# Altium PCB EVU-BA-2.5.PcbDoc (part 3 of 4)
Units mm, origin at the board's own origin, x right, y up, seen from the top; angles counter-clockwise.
Board outline 80 x 82.5 mm, 4 copper layers (Top Layer, Int1, Int2, Bottom Layer), stack 1.49 mm thick; 257 components, 201 nets, 889 pads, 696 vias.
Unrouted connection lines stored in the file: 1.
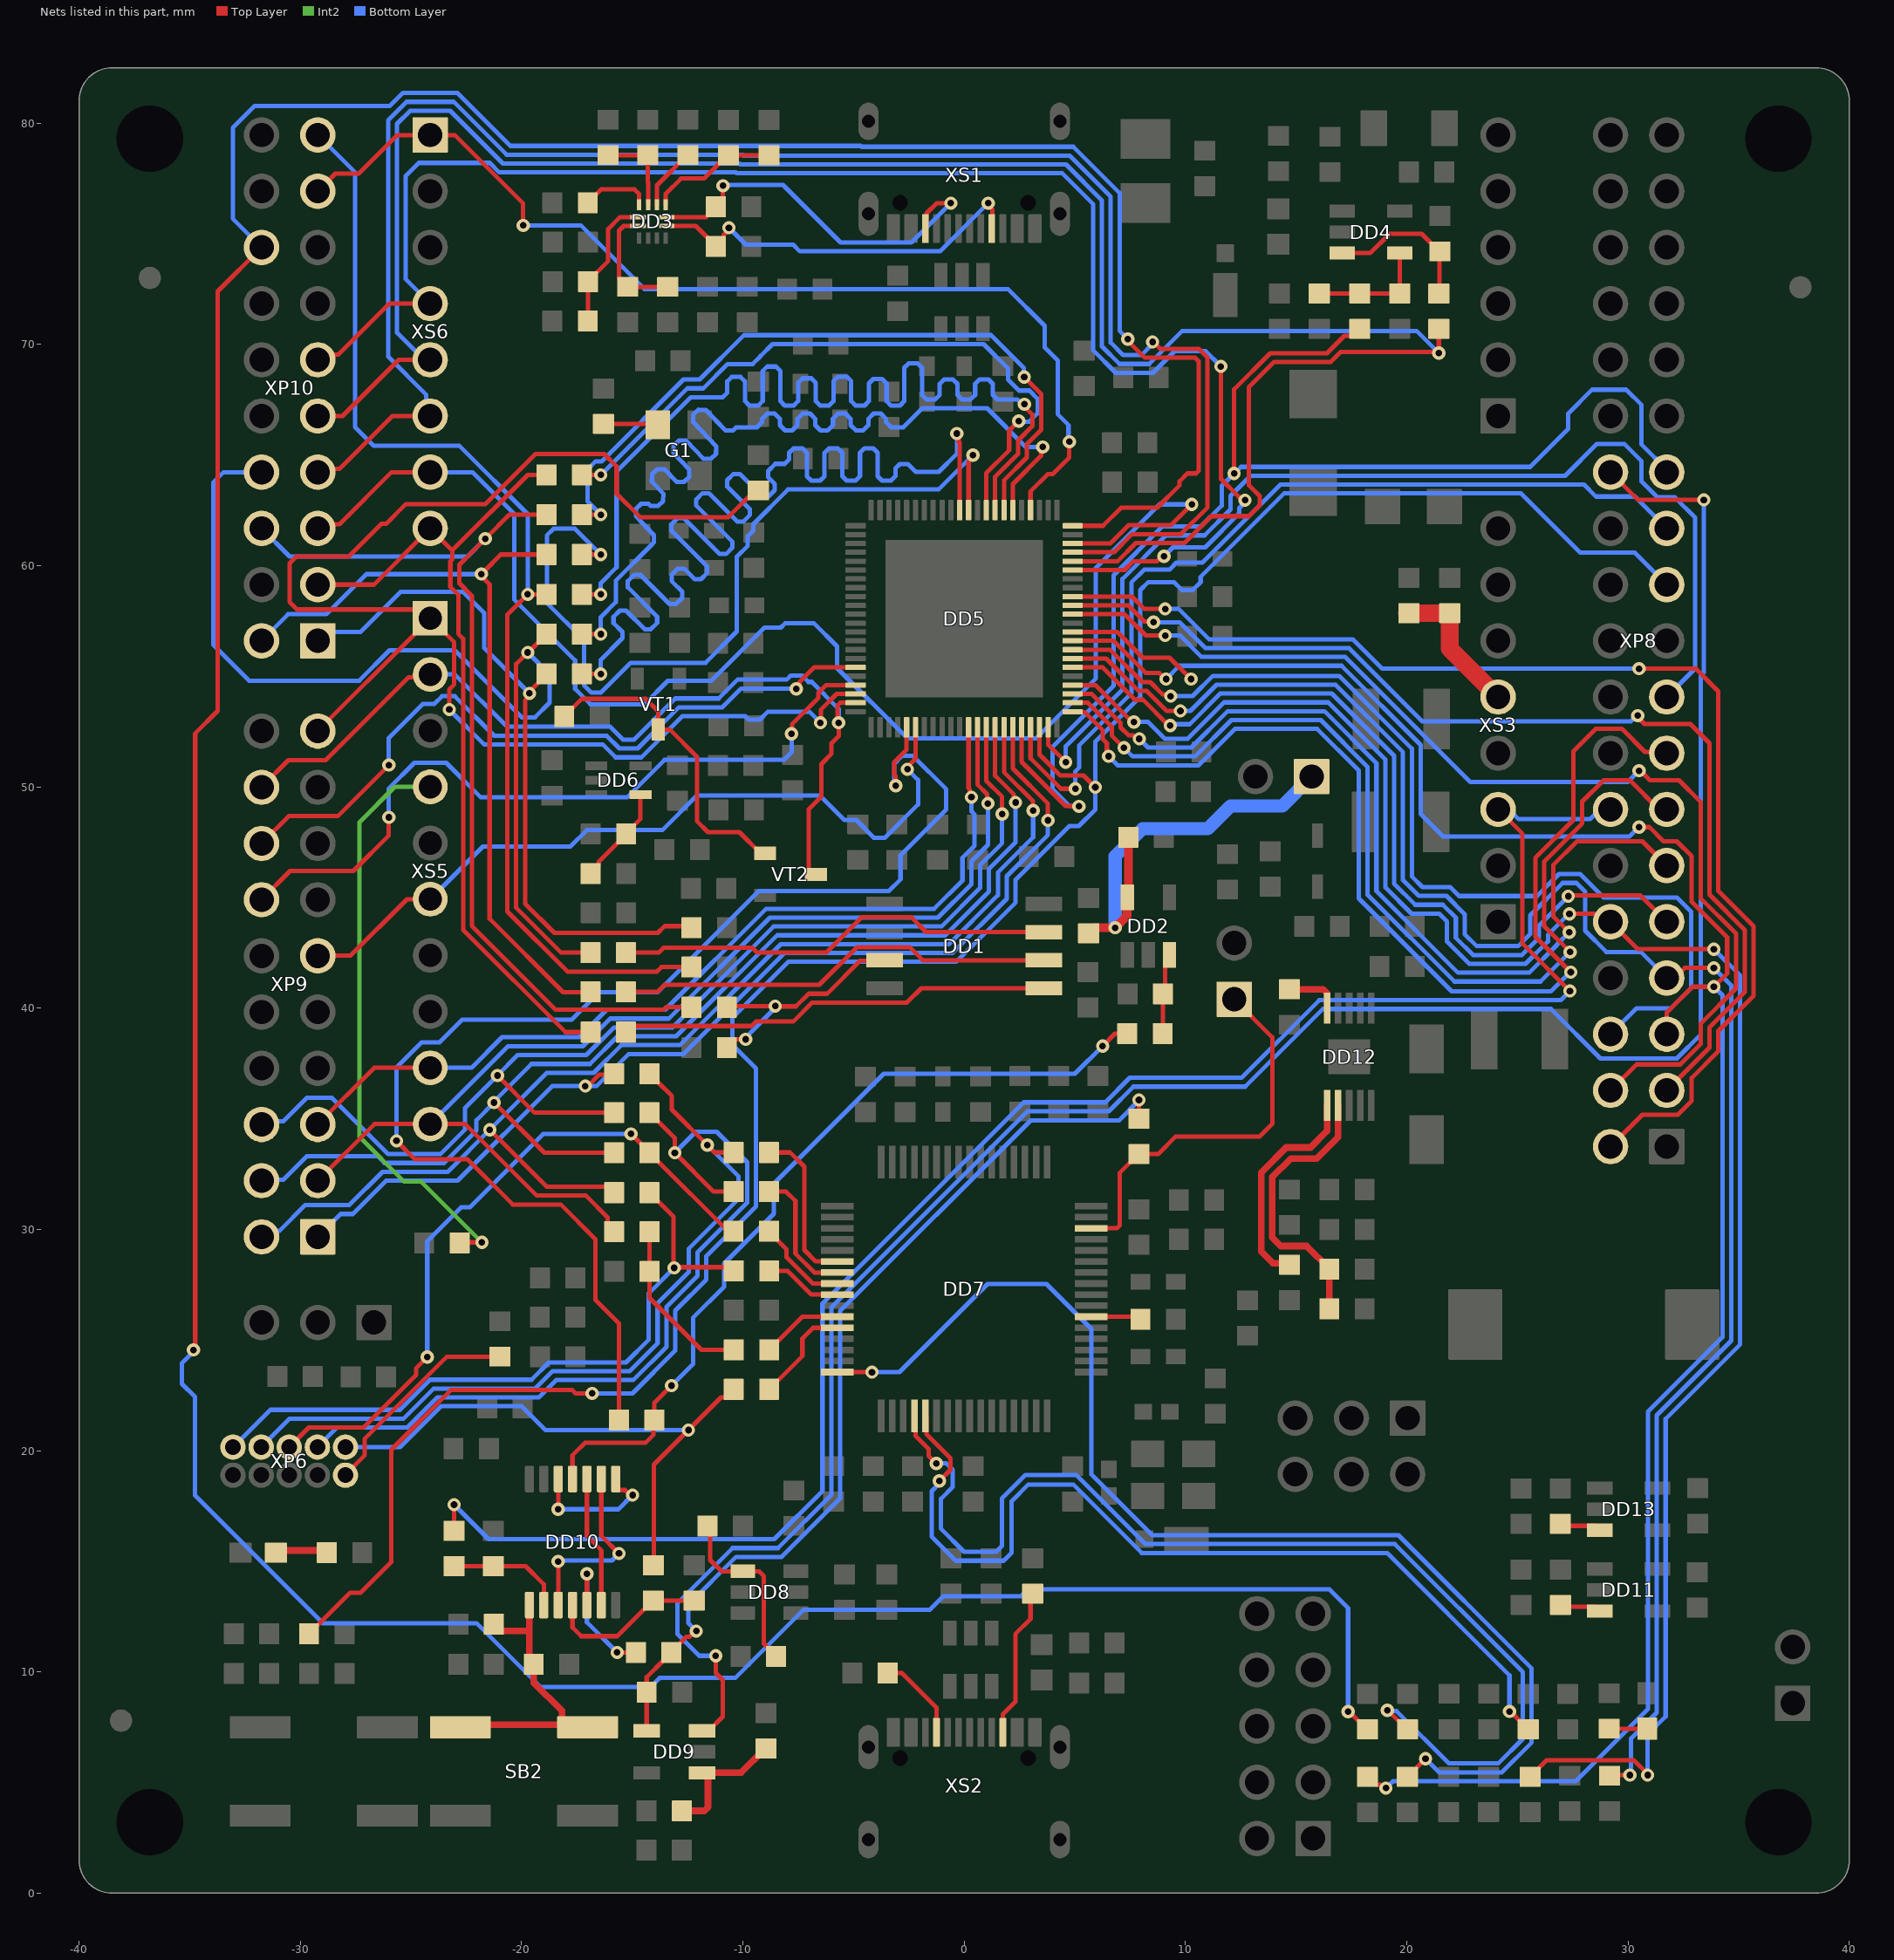
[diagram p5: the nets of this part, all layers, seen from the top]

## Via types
v1: diameter 0.6, hole 0.3, Top Layer to Bottom Layer, tented both sides, 670 vias
v2: diameter 0.6, hole 0.3, Top Layer to Bottom Layer, tented bottom, 26 vias

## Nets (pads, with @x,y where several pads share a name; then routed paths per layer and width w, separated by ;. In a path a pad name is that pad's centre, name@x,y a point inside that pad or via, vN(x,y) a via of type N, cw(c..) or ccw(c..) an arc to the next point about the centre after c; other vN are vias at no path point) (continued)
NetDD1_3: DD1.3 R2.2 R3.1 | length 11
  Top Layer w0.2: R2.2@-10.723,38.284 -10.417,38.589 v1(-9.873,38.589) ; R3.1@-10.723,40.039 -10.672,40.09 v1(-8.538,40.09) -8.524,40.076 -7.602,40.076 -7.028,40.65 -6.191,40.65 -4.708,42.133 -3.632,42.133 DD1.3@-3.6,42.165
  Bottom Layer w0.2: v1(-9.873,38.589) -9.873,38.672 -8.538,40.007 v1(-8.538,40.09)
NetDD1_5: DD1.5 R27.2 | length 19.7
  Top Layer w0.2: R27.2@-15.285,38.914 -15.01,39.189 -9.607,39.189 -9.407,39.389 -7.723,39.389 -6.862,40.25 -2.587,40.25 -1.942,40.895 DD1.5@3.6,40.895
NetDD1_6: DD1.6 R26.2 | length 20
  Top Layer w0.2: R26.2@-15.335,40.73 -13.863,40.73 -13.543,41.05 -6.546,41.05 -4.856,42.74 -2.444,42.74 -1.869,42.165 DD1.6@3.6,42.165
NetDD1_7: DD1.7 R25.2 | length 20
  Top Layer w0.2: R25.2@-15.285,42.505 -13.805,42.505 -13.58,42.73 -9.574,42.73 -9.349,42.505 -6.237,42.505 -4.643,44.1 -2.383,44.1 -1.718,43.435 DD1.7@3.6,43.435
NetDD2_3: DD2.3 R6.2 R8.2 | length 3.7
  Top Layer w0.2: R8.2@8.971,38.845 8.979,38.853 8.979,40.637 R6.2@8.987,40.645 9.075,40.733 9.075,42.205 DD2.3@9.275,42.405
NetDD2_5: DD2.5 R23.2 R24.1 XP2.1 | length 20
  Top Layer w0.4: R24.1@5.621,43.38 5.871,43.63 v1@6.867,43.63 ; v1(6.825,43.63) 7.368,44.173 DD2.5@7.368,44.864 ; 7.347,44.11 7.347,44.977 DD2.5@7.375,45.005 ; DD2.5@7.419,45.049 R23.2@7.419,47.72
  Bottom Layer w0.6: v1(6.825,43.63) 6.825,46.864 8.066,48.105 11.007,48.105 12.042,49.14 14.376,49.14 XP2.1@15.703,50.467
NetDD3_1: DD3.1 R15.2 XS1.A5 | length 18
  Top Layer w0.2: DD3.1@-13.436,75.352 -12.126,75.352 R15.2@-11.218,74.444 ; R15.2@-11.218,74.419 R15.2@-11.218,74.444 ; v1(-10.63,75.269) -10.63,75.191 -10.868,74.952 -10.868,74.794 R15.2@-11.218,74.444 ; v1(1.087,76.382) 1.087,76.274 1.27,76.091 1.27,75.25 XS1.A5@1.25,75.23
  Bottom Layer w0.2: v1(-10.63,75.269) -9.86,74.5 -7.723,74.5 -7.423,74.2 -1.095,74.2 v1(1.087,76.382)
NetDD3_2: DD3.2 R13.2 XS1.B5 | length 17.6
  Top Layer w0.2: DD3.2@-13.436,75.752 -11.661,75.752 -10.9,76.512 v1(-10.9,77.17) ; XS1.B5@-1.75,75.23 -1.7,75.28 -1.7,75.92 -1.249,76.372 -0.612,76.372 v1(-0.602,76.382)
  Bottom Layer w0.2: v1(-10.9,77.17) -10.87,77.2 -8.188,77.2 -5.588,74.6 -2.384,74.6 v1(-0.602,76.382)
NetDD3_3: DD3.3 R17.2 R112.2 | length 5.8
  Top Layer w0.2: DD3.3@-13.486,76.302 -13.486,76.8 -12.792,77.495 -11.758,77.495 -11.088,78.164 -11.088,78.189 R17.2@-10.738,78.539 ; R17.2@-10.659,78.54 R112.2@-8.823,78.54
NetDD3_4: DD3.4 R16.2 | length 2.8
  Top Layer w0.2: DD3.4@-13.886,76.302 -13.886,77.182 -12.516,78.552 R16.2@-12.491,78.552
NetDD3_5: DD3.5 R30.1 R32.1 | length 4.1
  Top Layer w0.2: R30.1@-16.098,78.552 R32.1@-14.294,78.552 -14.294,77.331 -14.286,77.323 DD3.5@-14.286,76.302
NetDD3_6: DD3.6 R34.1 | length 3.2
  Top Layer w0.2: R34.1@-17.01,76.393 -17.01,76.418 -16.66,76.768 -16.635,76.768 -16.403,77 -14.9,77 -14.686,76.786 DD3.6@-14.686,76.302
NetDD3_7: DD3.7 R28.1 R31.1 | length 6.1
  Top Layer w0.2: R28.1@-17.008,71.052 -17.002,71.058 -17.002,72.824 R31.1@-16.996,72.83 -16.996,72.855 -16.086,73.764 -16.086,75.214 -15.549,75.752 DD3.7@-14.736,75.752
NetDD3_8: DD3.8 R29.1 R33.1 | length 5.4
  Top Layer w0.2: R33.1@-15.244,72.634 -15.259,72.634 -15.575,72.95 -15.575,73.042 -15.6,73.067 -15.6,75.134 -15.383,75.352 DD3.8@-14.736,75.352 ; R33.1@-15.2,72.6 R29.1@-13.4,72.6
NetDD4_3: DD4.3 R36.1 R38.1 | length 7
  Top Layer w0.2: DD4.3@17.082,74.125 18.354,74.125 19.229,75 20.675,75 21.475,74.2 R38.1@21.5,74.2 21.475,74.175 21.475,72.325 R36.1@21.45,72.3
NetDD4_4: DD4.4 R42.1 R43.1 R44.1 | length 5.7
  Top Layer w0.2: R44.1@16.05,72.3 R43.1@17.879,72.3 R42.1@19.682,72.3 19.682,73.925 19.457,74.15 DD4.4@19.375,74.15
NetDD5_49: DD5.49 R116.2 | length 61
  Top Layer w0.2: v1(-25.65,34) -24.81,33.16 -22.436,33.16 -20.401,31.125 -18.231,31.125 -16.668,29.562 -16.668,26.819 -15.599,25.75 R116.2@-15.599,21.377 ; v1(-3.095,50.048) -3.104,50.058 -3.104,50.488 -3.164,50.547 -3.164,51.118 -2.6,51.682 DD5.49@-2.6,52.695
  Bottom Layer w0.2: v1(-25.65,34) -25.65,37.318 -24.51,38.458 -23.699,38.458 -22.674,39.483 -17.728,39.483 -16.486,40.725 -13.842,40.725 -9.277,45.29 -3.402,45.29 -2.876,45.816 -2.876,46.909 -0.809,48.976 -0.809,49.889 -2.315,51.395 -2.812,51.395 -3.164,51.044 -3.164,50.117 v1(-3.095,50.048)
NetDD5_76: DD5.76 X1.1 | length 6.2
  Top Layer w0.2: DD5.76@4.905,57 6.918,57 8.079,55.84 9.282,55.84 v2(10.25,54.872)
NetDD6_4: DD6.4 R54.2 R55.1 | length 4.5
  Top Layer w0.2: R55.1@-16.875,46.075 -16.525,46.425 -16.525,46.6 -15.275,47.85 R54.2@-15.275,47.875 -15.275,47.9 -14.625,48.55 DD6.4@-14.625,49.65
NetDD7_6: DD7.6 R61.2 | length 2.3
  Top Layer w0.2: DD7.6@5.738,26.05 7.783,26.05 R61.2@7.933,26.2
NetDD7_38: DD7.38 R69.1 | length 7.3
  Top Layer w0.2: R69.1@-8.818,33.473 -7.865,33.473 -7.225,32.833 -7.225,29.07 -6.705,28.55 DD7.38@-5.738,28.55
NetDD7_39: DD7.39 R64.1 | length 6
  Top Layer w0.2: R64.1@-8.818,31.704 -8.045,31.704 -7.625,31.285 -7.625,28.905 -6.771,28.05 DD7.39@-5.738,28.05
NetDD7_40: DD7.40 R65.1 | length 4.3
  Top Layer w0.2: R65.1@-8.822,29.893 -8.025,29.097 -8.025,28.739 -6.836,27.55 DD7.40@-5.738,27.55
NetDD7_41: DD7.41 R66.1 | length 3.5
  Top Layer w0.2: R66.1@-8.811,28.126 -7.978,28.126 -6.902,27.05 DD7.41@-5.738,27.05
NetDD7_43: DD7.43 R67.1 | length 3.7
  Top Layer w0.2: R67.1@-8.811,24.55 -8.811,24.575 -8.461,24.925 -8.436,24.925 -7.311,26.05 DD7.43@-5.738,26.05
NetDD7_44: DD7.44 R68.1 | length 4.7
  Top Layer w0.2: R68.1@-8.811,22.77 -8.811,22.795 -8.461,23.145 -8.436,23.145 -7.311,24.27 -7.311,25.067 -6.828,25.55 DD7.44@-5.738,25.55
NetDD7_48: DD7.48 R100.1 | length 54.2
  Top Layer w0.2: DD7.48@-5.738,23.55 -5.735,23.547 -4.169,23.547 v1(-4.166,23.545) ; R100.1@20.03,5.25 v1(20.85,6.07)
  Bottom Layer w0.2: v1(-4.166,23.545) -2.927,23.545 1.058,27.529 3.721,27.529 5.754,25.496 5.754,18.923 8.502,16.175 19.627,16.175 25.644,10.158 25.644,6.806 24.298,5.459 21.461,5.459 v1(20.85,6.07)
NetDD7_52: DD7.52 R101.1 | length 51.3
  Top Layer w0.2: DD7.52@-2.25,21.562 -2.2,21.512 -2.2,20.67 -1.6,20.07 -1.6,19.758 v1(-1.26,19.418) ; v1(19.127,8.263) 19.148,8.263 20.008,7.403 R101.1@20.033,7.403
  Bottom Layer w0.2: v1(-1.26,19.418) -1.257,19.421 -0.809,19.421 -0.518,19.13 -0.518,18.35 -1.045,17.823 -1.045,16.466 -0.003,15.424 1.44,15.424 1.711,15.695 1.711,17.844 2.766,18.9 5.066,18.9 8.191,15.775 19.462,15.775 25.244,9.992 25.244,6.972 24.132,5.859 21.909,5.859 19.54,8.228 19.163,8.228 v1(19.127,8.263)
NetDD7_53: DD7.53 R102.1 | length 42
  Top Layer w0.2: DD7.53@-1.75,21.562 -1.7,21.512 -1.7,20.736 -0.618,19.653 -0.618,19.131 v1(-1.118,18.631) ; v1(24.644,8.209) 24.689,8.209 25.117,7.781 25.117,7.756 25.467,7.406 R102.1@25.492,7.406
  Bottom Layer w0.2: v1(-1.118,18.631) -1.118,18.523 -1.469,18.172 -1.469,16.112 -0.381,15.024 1.789,15.024 2.15,15.385 2.15,17.718 2.901,18.469 4.931,18.469 8.025,15.375 19.113,15.375 24.644,9.843 v1(24.644,8.209)
NetDD8_1: DD8.1 R59.2 R60.2 | length 8.2
  Top Layer w0.2: R59.2@-11.6,16.596 -11.475,16.471 -11.475,15.054 -10.958,14.537 -10,14.537 -9.257,14.537 -9.05,14.33 -9.05,11.275 -8.5,10.725 R60.2@-8.5,10.7
NetDD9_1: DD9.1 R77.2 R79.1 | length 6.1
  Top Layer w0.3: R79.1@-12.755,3.717 -11.751,3.717 -11.575,3.893 DD9.1@-11.575,5.437 ; DD9.1@-11.85,5.437 DD9.1@-11.575,5.437 ; R77.2@-8.955,6.537 -8.98,6.537 -10.08,5.437 DD9.1@-11.575,5.437
NetDD10_2: DD10.2 R82.1 R83.1 | length 5.3
  Top Layer w0.2: R83.1@-23.051,14.775 R82.1@-21.275,14.775 -19.814,14.775 -18.997,13.958 DD10.2@-18.997,13.017
NetDD10_3: DD10.3 DD10.9 | length 8.6
  Top Layer w0.2: DD10.3@-18.347,13.017 v1(-18.347,14.991) ; DD10.9@-16.397,18.717 -16.397,16.152 v1(-15.597,15.352)
  Bottom Layer w0.2: v1(-18.347,14.991) -18.302,15.036 -15.914,15.036 v1@-15.598,15.352
NetDD10_4: DD10.4 R85.2 R86.1 | length 7.3
  Top Layer w0.2: DD10.4@-17.697,13.017 -17.697,12.008 -17.303,11.614 -15.673,11.614 -14.071,13.217 R85.2@-14.046,13.217 R86.1@-12.2,13.217
NetDD10_5: DD10.5 R84.1 | length 6.4
  Top Layer w0.2: DD10.5@-17.047,13.017 v1(-17.047,14.436) ; v1(-15.681,10.878) R84.1@-14.831,10.878
  Bottom Layer w0.2: v1(-17.047,14.436) -17.047,12.243 v1(-15.681,10.878)
NetDD10_6: DD10.6 DD10.10 | length 6
  Top Layer w0.2: DD10.10@-17.047,18.717 -17.047,16.142 -16.397,15.492 DD10.6@-16.397,13.017
NetDD10_8: DD10.8 DD10.12 | length 6.3
  Top Layer w0.2: v1(-18.347,17.35) DD10.12@-18.347,18.717 ; DD10.8@-15.747,18.717 -15.747,18.317 -15.647,18.217 -15.32,18.217 -15.091,17.989 v1(-14.983,17.989)
  Bottom Layer w0.2: v1(-18.347,17.35) -15.622,17.35 v1(-14.983,17.989)
NetDD11_3: DD11.3 R90.2 | length 1.9
  Top Layer w0.2: R90.2@26.95,13.025 27.025,12.95 28.525,12.95 DD11.3@28.725,12.75
NetDD12_5: DD12.5 R91.2 | length 2.4
  Top Layer w0.3: R91.2@14.7,40.852 16.224,40.852 16.4,40.676 DD12.5@16.4,40
NetDD12_6: DD12.6 R95.1 | length 10
  Top Layer w0.3: R95.1@14.7,28.4 14.628,28.472 13.951,28.472 13.425,28.998 13.425,32.568 14.557,33.7 15.65,33.7 16.4,34.45 DD12.6@16.4,35.6
NetDD12_7: DD12.7 R93.1 R94.2 | length 12.9
  Top Layer w0.3: R93.1@16.5,26.4 R94.2@16.5,28.2 16.5,28.225 15.481,29.244 14.319,29.244 13.925,29.639 13.925,32.361 14.764,33.2 15.929,33.2 16.9,34.171 DD12.7@16.9,35.6
NetDD13_3: DD13.3 R96.2 | length 1.9
  Top Layer w0.2: R96.2@26.936,16.69 27.026,16.6 28.525,16.6 DD13.3@28.725,16.4
NetG1_1: G1.1 R35.2 | length 2.5
  Top Layer w0.2: R35.2@-16.3,66.4 -13.89,66.4 G1.1@-13.85,66.36
NetLD1_2: LD1.2 R87.2 | length 1.7
  Top Layer w0.2: R87.2@29.148,7.433 LD1.2@30.872,7.433
NetLD2_2: LD2.2 R97.1 | length 2.3
  Top Layer w0.3: LD2.2@-31.201,15.487 R97.1@-28.901,15.487
NetR98_1: R98.1 XP6.9 | length 9.7
  Top Layer w0.2: XP6.9@-27.959,18.888 -27.959,18.92 -27.084,19.795 -27.084,20.538 -23.376,24.246 R98.1@-20.979,24.246
NetR103_2: R103.2 VT1.3 VT2.1 | length 14.5
  Top Layer w0.2: R103.2@-18.072,53.184 -18.072,53.209 -17.722,53.559 -17.697,53.559 -17.281,53.975 -14.381,53.975 -13.821,53.415 VT1.3@-13.821,52.59 -13.3,52.59 -12.075,51.365 -12.075,48.45 -11.578,47.953 -10.157,47.953 -9.198,46.993 VT2.1@-8.998,46.993
NetR109_1: R109.1 XS2.A5 | length 4.1
  Top Layer w0.2: R109.1@-3.456,9.944 -2.811,9.944 -1.25,8.384 XS2.A5@-1.25,7.175
NetR110_1: R110.1 XS2.B5 | length 6.8
  Top Layer w0.2: XS2.B5@1.751,7.176 1.751,8.08 2.313,8.643 2.313,11.707 3,12.394 R110.1@3,13.409
NetR115_1: R115.1 R118.1 XS3.5 | length 6.6
  Top Layer w0.8: R118.1@19.998,57.85 R115.1@21.942,57.85 21.942,56.248 XS3.5@24.13,54.06
NetR119_1: R119.1 XS5.4 | length 26.6
  Top Layer w0.2: R119.1@-22.797,29.388 -22.771,29.413 v1(-21.793,29.413)
  Int2 w0.2: XS5.4@-24.13,50 -25.726,50 -27.321,48.406 -27.321,34.171 -25.305,32.156 -24.536,32.156 v1(-21.793,29.413)
nRESET: DD9.4 R56.1 R81.1 R84.2 | length 42.6
  Top Layer w0.2: DD9.4@-14.35,7.337 -14.346,7.341 -14.346,9.764 -13.606,10.503 -13.581,10.503 -13.231,10.853 -13.231,10.903 -12.558,11.576 -12.422,11.576 -12.152,11.845 v1(-12.104,11.845) ; v1(7.9,35.85) 7.9,35.017 R56.1@7.951,34.966
  Bottom Layer w0.2: v1(-12.104,11.845) -12.471,12.211 -12.471,13.026 -10.301,15.196 -8.245,15.196 -5.603,17.839 -5.603,26.313 3.007,34.923 6.998,34.923 7.9,35.825 v1(7.9,35.85)
nRST_ALL: DD9.3 XP8.26 | length 100.3
  Top Layer w0.2: DD9.3@-11.85,7.337 -11.55,7.337 -10.909,7.977 -10.909,9.632 -11.227,9.949 v1(-11.227,10.725) ; XP8.26@29.21,64.22 30.463,62.967 v1(33.423,62.967)
  Bottom Layer w0.2: v1(-11.227,10.725) -11.975,10.725 -12.951,11.701 -12.951,13.112 -10.467,15.596 -8.411,15.596 -6.003,18.004 -6.003,26.479 2.858,35.34 6.542,35.34 7.651,36.45 12.703,36.45 16.21,39.958 26.517,39.958 28.754,37.72 31.169,37.72 32.206,37.72 33.28,38.794 33.28,55.024 33.43,55.174 33.43,62.961 v1(33.423,62.967)
nRST_FTDI: DD7.14 R56.2 XP3.1 | length 17.9
  Top Layer w0.2: DD7.14@5.738,30.05 6.908,30.05 7.025,30.167 7.025,32.55 7.875,33.4 R56.2@7.9,33.4 8.764,33.4 9.564,34.2 13.359,34.2 13.925,34.766 13.925,38.68 XP3.1@12.205,40.4
nRST_MCU: DD10.11 R8.1 R116.1 | length 37.5
  Top Layer w0.2: DD10.11@-17.697,18.717 -17.697,19.417 -17.697,19.79 -17.139,20.348 -14.406,20.348 -14.034,20.72 -14.034,21.342 R116.1@-13.999,21.377 ; R116.1@-13.999,21.352 -13.999,22.16 v1(-13.221,22.938) ; v1(6.258,38.286) 6.817,38.845 R8.1@7.371,38.845 R8.1@7.371,38.82
  Bottom Layer w0.2: v1(-13.221,22.938) -12.253,23.907 -12.253,25.998 -10.851,27.4 -10.851,28.459 -8.604,30.705 -8.604,32.063 -3.638,37.029 5.001,37.029 v1(6.258,38.286)
nRST_U: R83.2 XP8.14 XS3.3 | length 82.5
  Top Layer w0.2: R83.2@-23.051,16.375 v1(-23.051,17.555) ; XS3.3@24.13,48.98 25.23,47.88 25.23,42.917 v1(27.375,40.772)
  Bottom Layer w0.2: v1(-23.051,17.555) -21.492,15.996 -8.576,15.996 -6.403,18.17 -6.403,26.645 2.693,35.74 6.376,35.74 7.486,36.85 12.537,36.85 16.045,40.358 26.961,40.358 v1(27.375,40.772) ; XS3.3@24.13,48.98 24.398,48.712 24.885,48.712 25.061,48.536 28.279,48.536 28.455,48.712 28.942,48.712 XP8.14@29.21,48.98
nSRST: R68.2 R85.1 XP6.10 | length 26.3
  Top Layer w0.2: R85.1@-14.046,14.817 -14.021,14.842 -14.021,19.366 v1(-12.462,20.925) -10.982,22.405 -10.761,22.405 -10.411,22.755 R68.2@-10.411,22.77 ; R68.2@-10.324,22.685 R68.2@-10.307,22.669
  Bottom Layer w0.2: XP6.10@-27.959,20.158 -25.486,20.158 -23.64,22.004 -19.998,22.004 -18.918,20.925 v1(-12.462,20.925)
nVBUS_FLG_USB/PB14: DD5.84 R36.2 XP10.9 XS6.5 | length 99.9
  Top Layer w0.2: XP10.9@-29.21,66.76 -28.093,66.76 -25.553,69.3 XS6.5@-24.13,69.3 ; DD5.84@4.905,60.2 6.175,60.2 6.939,60.2 7.76,61.021 9.955,61.021 11.168,62.234 12.865,62.234 13.358,62.727 13.358,63.14 12.863,63.634 12.863,68.067 13.997,69.2 16.561,69.2 17.013,69.653 21.403,69.653 v1(21.45,69.606) R36.2@21.45,70.7
  Bottom Layer w0.2: XS6.5@-24.13,69.3 -24.4,69.3 -25.63,70.53 -25.63,79.961 -25.031,80.56 -23.229,80.56 -20.839,78.17 -10.157,78.17 -10.117,78.13 4.27,78.13 4.602,78.13 6.223,76.509 6.223,76.177 6.223,69.908 7.02,69.112 8.365,69.112 9.859,70.606 20.45,70.606 v1(21.45,69.606)
PA13: DD5.42 R114.1 XP9.19 XS5.1 | length 67.3
  Top Layer w0.2: XP9.19@-29.21,52.53 -24.818,56.923 -24.818,56.933 XS5.1@-24.13,57.62 ; v1(-23.267,53.495) -23.267,54.405 -23.042,54.63 -23.042,56.533 XS5.1@-24.13,57.62 ; R114.1@-9.3,63.521 -9.325,63.521 -10.657,62.189 -14.642,62.189 -15.706,63.253 -15.706,64.483 -16.264,65.041 -19.368,65.041 -21.63,62.78 -25.225,62.78 -26.125,61.88 -26.343,61.88 -27.811,60.412 -30.176,60.412 -30.482,60.106 -30.482,58.355 -30.143,58.016 -24.526,58.016 XS5.1@-24.13,57.62 ; v1(-6.497,52.897) -6.467,52.926 -6.467,53.497 -5.764,54.2 DD5.42@-4.905,54.2
  Bottom Layer w0.2: v1(-23.267,53.495) -21.68,51.909 -16.322,51.909 -15.747,51.334 -14.587,51.334 -12.726,53.195 -9.887,53.195 -9.729,53.037 -9.229,53.037 -8.869,53.398 -6.997,53.398 v1(-6.497,52.897)
PA14: DD5.41 XP9.14 | length 34.3
  Top Layer w0.2: XP9.14@-31.75,44.91 -30.46,46.2 -27.6,46.2 -26,47.8 v1(-26,48.622) ; v1(-7.8,52.398) -7.78,52.418 -7.78,52.826 -6.589,54.017 -6.589,54.249 -6.238,54.6 DD5.41@-4.905,54.6
  Bottom Layer w0.2: v1(-26,48.622) -26,49.932 -24.844,51.088 -23.407,51.088 -21.843,49.523 -15.231,49.523 -13.54,51.213 -13.517,51.213 -13.498,51.232 -8.129,51.232 -7.8,51.56 v1(-7.8,52.398)
PA15: DD5.39 XP9.16 | length 32.9
  Top Layer w0.2: XP9.16@-31.75,47.45 -30.523,48.677 -28.306,48.677 v1(-26,50.983) ; v1(-7.589,54.431) -7.589,54.539 -7.446,54.683 -7.446,54.736 -6.782,55.4 DD5.39@-4.905,55.4
  Bottom Layer w0.2: v1(-26,50.983) -26,52.208 -24.464,53.744 -23.943,53.744 -23.591,54.095 -23.018,54.095 -21.232,52.309 -16.156,52.309 -15.581,51.734 -14.753,51.734 -12.892,53.595 -10.93,53.595 -10.079,54.445 -8.909,54.445 -7.603,54.445 v1(-7.589,54.431)
PB0: DD5.12 R53.1 | length 54.6
  Top Layer w0.2: R53.1@-17.272,55.1 v1(-16.422,55.1) ; v1(-0.33,65.968) -0.253,65.891 -0.253,65.608 -0.2,65.555 DD5.12@-0.2,62.505
  Bottom Layer w0.2: v1(-16.422,55.1) -16.422,55.741 -15.516,56.647 -15.445,56.717 -15.445,57 -15.846,57.401 -15.846,57.683 -15.563,57.966 -15.28,57.966 -14.44,57.126 -14.157,57.126 -13.874,57.409 -13.874,57.692 -15.199,59.017 -15.199,59.299 -14.916,59.582 -14.633,59.582 -13.308,58.257 -13.025,58.257 -12.743,58.54 -12.743,58.823 -13.219,59.299 -13.219,59.582 -12.936,59.865 -12.653,59.865 -12.177,59.389 -11.894,59.389 -11.611,59.671 -11.611,59.954 -13.235,61.578 -13.235,61.861 -12.952,62.144 -12.67,62.144 -11.046,60.52 -10.763,60.52 -10.48,60.803 -10.48,61.086 -12.104,62.71 -12.104,62.993 -11.821,63.275 -11.538,63.275 -10.256,61.993 -9.973,61.993 -9.69,62.276 -9.69,62.559 -10.707,63.575 -10.707,63.858 -10.424,64.141 -10.141,64.141 -9.124,63.124 -8.841,63.124 -8.559,63.407 -8.559,63.69 -8.859,63.99 -8.859,64.273 -8.531,64.6 -8.252,64.6 -8.208,64.6 -8.108,64.6 -7.908,64.8 -7.908,65.103 -7.708,65.303 -7.308,65.303 -7.108,65.103 -7.108,64.038 -6.908,63.838 -6.508,63.838 -6.308,64.038 -6.308,65.103 -6.108,65.303 -5.708,65.303 -5.508,65.103 -5.508,64.038 -5.308,63.838 -4.908,63.838 -4.708,64.038 -4.708,65.103 -4.508,65.303 -4.108,65.303 -3.908,65.103 -3.908,64.038 -3.708,63.838 -3.308,63.838 -3.108,64.038 -3.108,64.39 -2.908,64.59 -2.625,64.59 -2.541,64.59 -2.188,64.238 -1.282,64.238 -1.147,64.238 -0.33,65.054 v1(-0.33,65.968)
PB1: DD5.11 R47.1 | length 38.5
  Top Layer w0.2: R47.1@-17.272,60.5 v1(-16.422,60.5) ; DD5.11@0.2,62.505 0.2,62.865 0.2,64.687 0.4,64.887 v1(0.4,64.995)
  Bottom Layer w0.2: v1(-16.422,60.5) -17.597,61.675 -18.545,61.675 -18.857,61.362 -18.857,58.311 -17.179,56.633 -17.179,54.59 -16.847,54.257 -16.416,54.257 -15.068,55.605 -11.685,55.605 -10.275,57.015 -10.275,60.4 -9.779,60.896 -9.779,61.331 -9.529,61.58 -9.529,61.871 -7.963,63.438 -1.157,63.438 v1(0.4,64.995)
PB2: DD5.9 R48.1 | length 30.7
  Top Layer w0.2: R48.1@-17.272,64.1 v1(-16.422,64.1) ; DD5.9@1,62.505 1,64.181 2.034,65.214 2.034,66.105 v1(2.464,66.535)
  Bottom Layer w0.2: v1(-16.422,64.1) -12.512,68.01 -11.786,68.01 -10.687,69.109 -9.556,69.109 -9.204,69.46 -9.204,69.47 -8.66,70.014 0.885,70.014 1.978,68.921 1.978,68.411 2.477,67.912 2.949,67.912 3.32,67.541 3.32,66.885 2.941,66.506 2.492,66.506 v1(2.464,66.535)
PB3: DD5.8 R49.1 | length 48.9
  Top Layer w0.2: R49.1@-17.272,58.8 -17.172,58.7 v1(-16.422,58.7) ; DD5.8@1.4,62.505 1.4,62.865 1.4,64.015 2.434,65.049 2.434,65.656 3.082,66.304 3.082,66.822 2.72,67.184 v1(2.72,67.292)
  Bottom Layer w0.2: v1(-16.422,58.7) -16.422,59.208 -15.706,59.924 -15.706,64.25 -12.346,67.61 -11.004,67.61 -10.904,67.61 -10.704,67.81 -10.704,68.326 -10.504,68.526 -10.104,68.526 -9.904,68.326 -9.904,67.433 -9.704,67.233 -9.304,67.233 -9.104,67.433 -9.104,68.795 -8.904,68.995 -8.504,68.995 -8.304,68.795 -8.304,67.433 -8.104,67.233 -7.704,67.233 -7.504,67.433 -7.504,68.262 -7.304,68.462 -6.904,68.462 -6.704,68.262 -6.704,67.433 -6.504,67.233 -6.104,67.233 -5.904,67.433 -5.904,68.339 -5.704,68.539 -5.304,68.539 -5.104,68.339 -5.104,67.433 -4.904,67.233 -4.504,67.233 -4.304,67.433 -4.304,68.237 -4.104,68.437 -3.704,68.437 -3.504,68.237 -3.504,67.433 -3.304,67.233 -2.904,67.233 -2.704,67.433 -2.704,68.947 -2.504,69.147 -2.104,69.147 -1.904,68.947 -1.904,67.712 -1.704,67.512 -1.304,67.512 -1.104,67.712 -1.104,68.212 -0.904,68.412 -0.504,68.412 -0.304,68.212 -0.304,67.712 -0.104,67.512 0.296,67.512 0.496,67.712 0.496,68.212 0.696,68.412 1.096,68.412 1.296,68.212 1.296,67.712 1.496,67.512 1.721,67.512 2.403,67.512 2.622,67.292 v1(2.72,67.292)
PB4: DD5.7 R50.1 | length 33.4
  Top Layer w0.2: R50.1@-17.272,62.3 v1(-16.422,62.3) ; DD5.7@1.8,62.505 1.8,63.849 2.834,64.883 2.834,65.49 3.482,66.138 3.482,67.756 v1(2.716,68.521)
  Bottom Layer w0.2: v1(-16.422,62.3) -17.022,62.9 -17.022,64.349 -16.67,64.7 -16.387,64.7 -12.678,68.41 -11.952,68.41 -9.948,70.414 1.215,70.414 2.688,68.941 2.688,68.55 v1(2.716,68.521)
PB5: DD5.6 R51.1 | length 43.6
  Top Layer w0.2: R51.1@-17.272,56.8 -17.172,56.9 v1(-16.422,56.9) ; DD5.6@2.2,62.505 2.2,63.441 2.2,63.684 3.477,64.961 3.477,65.285 v1(3.553,65.362)
  Bottom Layer w0.2: v1(-16.422,56.9) -16.422,57.673 -15.744,58.351 -15.744,59.32 -14.098,60.966 -14.028,61.037 -14.019,61.376 -14.835,62.235 -14.826,62.574 -14.594,62.795 -14.255,62.786 -14.175,62.702 -13.835,62.693 -13.603,62.914 -13.595,63.253 -14.111,63.796 -14.102,64.136 -13.87,64.356 -13.531,64.347 -13.002,63.791 -12.663,63.782 -12.431,64.002 -12.422,64.342 -13.136,65.093 -13.127,65.432 -12.895,65.653 -12.556,65.644 -11.785,64.833 -11.446,64.824 -11.214,65.044 -11.205,65.383 -12.251,66.485 -12.242,66.824 -12.01,67.044 -11.671,67.036 -10.792,66.11 -10.453,66.101 -10.307,66.247 -9.483,66.247 -9.469,66.247 -9.369,66.247 -9.129,66.487 -9.129,66.633 -8.889,66.873 -8.569,66.873 -8.329,66.633 -8.329,66.343 -8.089,66.103 -7.769,66.103 -7.529,66.343 -7.529,66.633 -7.289,66.873 -6.969,66.873 -6.729,66.633 -6.729,66.343 -6.489,66.103 -6.169,66.103 -5.929,66.343 -5.929,66.633 -5.689,66.873 -5.369,66.873 -5.129,66.633 -5.129,66.343 -4.889,66.103 -4.569,66.103 -4.329,66.343 -4.329,66.633 -4.089,66.873 -3.769,66.873 -3.529,66.633 -3.529,66.487 -3.289,66.247 -2.753,66.247 -2.142,66.859 -1.889,67.112 1.038,67.112 2.788,65.362 v1(3.553,65.362)
PB10: DD5.88 R10.2 XP10.16 | length 192.5
  Top Layer w0.2: v1(-34.825,24.549) -34.75,24.624 -34.75,52.414 -33.731,53.433 -33.731,72.399 XP10.16@-31.75,74.38 ; DD5.88@4.905,61.8 6.276,61.8 7.097,62.621 8.727,62.621 9.736,63.63 9.736,63.813 10.087,64.164 10.483,64.164 10.6,64.281 10.6,69.234 10.444,69.39 8.168,69.39 v1@7.399,70.16 ; v1@17.4,8.203 R10.2@18.2,7.403
  Bottom Layer w0.2: v1(-34.825,24.549) -34.825,24.476 -35.35,23.951 -35.35,23.02 -34.752,22.423 -34.752,17.973 -28.979,12.2 -22.039,12.2 -19.161,9.322 -14.165,9.322 -13.762,9.725 -10.341,9.725 -7.253,12.813 -1.54,12.813 -0.929,13.424 2.571,13.424 2.877,13.73 16.503,13.73 17.35,12.883 v1(17.35,8.203) ; XP10.16@-31.75,74.38 -33.05,75.68 -33.05,79.785 -32.065,80.77 -25.952,80.77 -25.362,81.36 -22.898,81.36 -20.508,78.97 -4.676,78.97 -4.636,78.93 4.934,78.93 7.023,76.84 7.023,70.609 v1(7.399,70.234)
PC1: DD5.80 XP8.2 | length 55.8
  Top Layer w0.2: DD5.80@4.905,58.6 7.403,58.6 7.581,58.6 8.141,58.04 v1(9.084,58.04) ; XP8.2@29.21,33.74 30.65,35.18 32.25,35.18 32.88,35.81 32.88,36.844 34.08,38.044 34.08,38.089 34.08,38.961 35.68,40.561 35.68,43.696 34.08,45.296 34.08,54.32 33.06,55.34 v1(30.5,55.34)
  Bottom Layer w0.2: v1(9.084,58.04) 9.697,58.04 11.066,56.671 17.554,56.671 18.886,55.34 v1(30.5,55.34)
PC2: DD5.79 XP8.3 | length 49.4
  Top Layer w0.2: DD5.79@4.905,58.2 7.415,58.2 8.141,57.474 8.52,57.474 v1(8.555,57.44) ; v1(30.443,53.22) 30.443,53.136 30.742,52.836 32.814,52.836 33.68,51.97 33.68,45.13 35.28,43.53 35.28,40.727 33.68,39.127 33.68,38.21 XP8.3@31.75,36.28
  Bottom Layer w0.2: v1(8.555,57.44) 9.732,57.44 10.9,56.272 17.388,56.272 20.7,52.96 30.126,52.96 30.386,53.22 v1(30.443,53.22)
PC3: DD5.78 XP8.4 | length 49.5
  Top Layer w0.2: DD5.78@4.905,57.8 7.25,57.8 8.21,56.84 v1(9.084,56.84) ; XP8.4@29.21,36.28 30.386,37.456 32.36,37.456 33.28,38.376 33.28,39.292 34.88,40.892 34.88,43.365 33.28,44.965 33.28,49.32 32.3,50.3 30.996,50.3 30.568,50.727 v1(30.5,50.727)
  Bottom Layer w0.2: v1(9.084,56.84) 9.758,56.84 10.726,55.872 17.223,55.872 22.873,50.221 29.984,50.221 30.49,50.727 v1(30.5,50.727)
PC4: DD5.75 R9.1 XP8.5 | length 93.7
  Top Layer w0.2: DD5.75@4.905,56.6 6.753,56.6 8.199,55.154 8.808,55.154 9.09,54.872 v1(9.125,54.872) ; R9.1@18.225,5.25 18.25,5.25 18.6,4.9 18.801,4.9 18.952,4.749 v1(19.06,4.749) ; v1(30.5,48.178) 30.968,48.178 31.606,47.54 32.206,47.54 32.88,46.866 32.88,44.799 34.48,43.199 34.48,41.558 v1@33.873,40.95 ; XP8.5@31.75,38.82 31.75,39.804 32.911,40.965 v1(33.88,40.965)
  Bottom Layer w0.2: v1(9.125,54.872) 9.725,55.472 17.057,55.472 20.631,51.898 20.631,48.772 21.644,47.759 30.062,47.759 30.481,48.178 v1@30.497,48.178 ; v1(19.06,4.749) 19.067,4.749 19.377,5.059 27.643,5.059 30.9,8.316 30.9,21.763 34.268,25.132 34.268,40.577 v1(33.88,40.965)
PC5: DD5.74 XP8.6 | length 45.8
  Top Layer w0.2: DD5.74@4.905,56.2 6.382,56.2 6.587,56.2 8.054,54.733 8.415,54.733 8.973,54.175 9.256,54.175 v1(9.332,54.099)
  Bottom Layer w0.2: v1(9.332,54.099) 10.326,54.099 11.244,55.017 16.946,55.017 20.231,51.732 20.231,48.606 20.231,47.501 20.231,45.952 20.713,45.47 21.964,45.47 22.37,45.064 25.888,45.064 26.881,46.056 27.833,46.056 28.889,45 32.206,45 32.85,44.356 32.85,40.904 31.942,39.996 30.386,39.996 XP8.6@29.21,38.82
PC6: DD5.73 R108.1 XP8.7 | length 83.6
  Top Layer w0.2: DD5.73@4.905,55.8 5.856,55.8 6.421,55.8 7.888,54.333 8.249,54.333 9.151,53.431 v1(9.773,53.431) ; R108.1@29.165,5.306 29.195,5.336 v1(30.087,5.336) ; XP8.7@31.75,41.36 32.114,41.36 32.567,41.814 v1(33.88,41.814)
  Bottom Layer w0.2: v1(9.773,53.431) 10.224,53.431 11.41,54.617 16.78,54.617 19.831,51.566 19.831,45.787 20.547,45.07 21.798,45.07 22.618,44.25 22.618,43.342 23.16,42.8 25.036,42.8 25.58,43.344 25.58,44.19 27.046,45.656 27.667,45.656 28.059,45.265 28.059,43.495 29.018,42.536 30.574,42.536 XP8.7@31.75,41.36 ; v1(30.087,5.336) 30.14,5.388 30.14,6.991 31.3,8.151 31.3,21.598 34.668,24.966 34.668,41.025 v1@33.881,41.813
PC7: DD5.72 XP8.9 | length 39.3
  Top Layer w0.2: DD5.72@4.905,55.4 6.256,55.4 7.265,54.391 7.722,53.933 8.083,53.933 9.242,52.775 v1(9.315,52.775) ; v1(27.3,45.056) 27.331,45.087 30.563,45.087 XP8.9@31.75,43.9
  Bottom Layer w0.2: v1(9.315,52.775) 9.371,52.831 10.189,52.831 11.576,54.217 16.614,54.217 19.431,51.401 19.431,45.621 20.382,44.67 21.632,44.67 22.218,44.084 22.218,43.176 22.994,42.4 25.202,42.4 25.98,43.178 25.98,43.737 v1(27.3,45.056)
PC8: DD5.70 R12.1 XP8.10 | length 86.7
  Top Layer w0.2: DD5.70@4.905,54.6 5.924,54.6 7.591,52.933 v1(7.669,52.933) ; R12.1@25.572,5.256 25.597,5.256 25.947,5.606 25.947,5.631 26.322,6.006 30.266,6.006 30.887,5.384 v1(30.887,5.336) ; v1(27.355,44.258) 28.473,44.258 28.831,43.9 XP8.10@29.21,43.9 30.448,42.662 v1(33.88,42.662)
  Bottom Layer w0.2: v1(7.669,52.933) 8.308,52.933 9.066,52.175 10.099,52.175 11.741,53.817 16.449,53.817 19.031,51.235 19.031,45.455 20.216,44.27 21.467,44.27 21.818,43.919 21.818,43.011 22.829,42 25.367,42 26.38,43.013 26.38,43.312 27.327,44.258 v1(27.355,44.258) ; v1(30.887,5.336) 30.887,7.173 31.7,7.985 31.7,21.432 35.068,24.8 35.068,41.474 v1(33.88,42.662)
PC9: DD5.69 XP8.11 | length 42.6
  Top Layer w0.2: DD5.69@4.905,54.2 5.759,54.2 7.069,52.889 7.069,52.685 7.421,52.333 7.645,52.333 7.807,52.172 v1(7.915,52.172) ; v1(27.341,43.424) 26.618,44.146 26.618,46.463 27.695,47.54 30.65,47.54 XP8.11@31.75,46.44
  Bottom Layer w0.2: v1@7.926,52.161 8.312,51.775 10.265,51.775 11.907,53.417 16.283,53.417 18.631,51.069 18.631,45.29 22.321,41.6 25.533,41.6 26.78,42.847 26.78,42.863 v1(27.341,43.424)
PC10: DD5.68 XP8.13 | length 46
  Top Layer w0.2: DD5.68@4.905,53.8 5.593,53.8 6.669,52.724 6.669,52.322 v1(7.226,51.766) ; v1(27.38,42.536) 26.218,43.698 26.218,46.629 27.93,48.34 27.93,49.33 28.9,50.3 30.079,50.3 31.399,48.98 XP8.13@31.75,48.98
  Bottom Layer w0.2: v1(7.226,51.766) 7.617,51.375 10.43,51.375 12.073,53.017 16.117,53.017 18.231,50.904 18.231,45.124 22.155,41.2 26.044,41.2 v1(27.38,42.536)
PC11: DD5.67 XP8.15 | length 49.8
  Top Layer w0.2: DD5.67@4.905,53.4 4.925,53.38 5.447,53.38 6.269,52.558 6.269,52.151 6.448,51.972 6.448,51.456 v1(6.525,51.38) ; v1(27.415,41.625) 25.818,43.222 25.818,46.795 27.53,48.506 27.53,51.606 28.544,52.62 29.725,52.62 30.767,51.578 31.692,51.578 XP8.15@31.75,51.52
  Bottom Layer w0.2: v1(6.525,51.38) 6.93,50.975 10.596,50.975 12.238,52.617 15.952,52.617 17.831,50.738 17.831,44.958 22.031,40.758 26.512,40.758 27.38,41.625 v1(27.415,41.625)
PC12: DD5.65 XP8.17 | length 50.6
  Top Layer w0.2: DD5.65@3.8,52.695 3.8,51.905 v1(4.592,51.113)
  Bottom Layer w0.2: v1(4.592,51.113) 4.592,51.836 7.155,54.399 7.155,59.4 9.121,61.366 10.866,61.366 12.036,62.536 12.036,63.152 12.944,64.06 27.157,64.06 28.599,65.502 29.829,65.502 30.611,64.719 30.611,63.803 31.333,63.081 32.119,63.081 33.03,62.17 33.03,55.34 XP8.17@31.75,54.06
PC13: DD5.64 R22.2 XP8.21 | length 105.7
  Top Layer w0.2: R22.2@-29.601,11.722 -29.601,11.747 -29.251,12.097 -29.226,12.097 -27.749,13.575 -27.273,13.575 -25.884,14.964 -25.884,20.041 -23.179,22.746 -17.715,22.746 -17.556,22.586 v1(-16.813,22.586) ; DD5.64@3.4,52.695 3.4,52.274 3.4,51.457 4.343,50.513 5.393,50.513 v1(5.925,49.982)
  Bottom Layer w0.2: v1(-16.813,22.586) -14.988,22.586 -13.053,24.521 -13.053,26.33 -11.651,27.732 -11.651,28.79 -9.404,31.037 -9.404,37.272 -10.473,38.341 -10.473,39.569 -7.952,42.09 -0.359,42.09 2.325,44.773 2.325,45.8 4.751,48.225 5.179,48.225 5.925,48.971 v1(5.925,49.982) 5.925,52.038 7.955,54.068 7.955,58.888 8.306,59.24 9.499,59.24 9.839,58.9 10.336,58.9 10.687,59.251 10.687,59.491 14.457,63.26 25.17,63.26 27.85,60.58 30.31,60.58 XP8.21@31.75,59.14
PC14: DD5.63 XP8.23 | length 41.2
  Top Layer w0.2: DD5.63@3,52.695 3,52.335 3,51.291 4.178,50.113 ; 4.178,50.113 4.378,49.913 v1(5.025,49.913)
  Bottom Layer w0.2: v1(5.025,49.913) 5.025,50.698 5.192,50.865 5.192,51.87 7.555,54.233 7.555,59.234 8.142,59.821 9.284,59.821 9.597,60.135 10.766,60.135 14.291,63.66 28.01,63.66 28.55,63.12 30.31,63.12 XP8.23@31.75,61.68
PC15: DD5.62 R43.2 XP8.25 | length 60.1
  Top Layer w0.2: DD5.62@2.6,52.695 2.6,51.125 4.587,49.139 5.167,49.139 v1(5.187,49.12) ; v1(12.2,64.164) 12.2,67.969 13.831,69.6 16.395,69.6 17.178,70.384 17.562,70.384 R43.2@17.879,70.7
  Bottom Layer w0.2: v1(5.187,49.12) 5.175,49.131 4.75,49.131 3.992,49.889 3.992,51.801 6.755,54.565 6.755,59.566 8.955,61.766 10.7,61.766 11.636,62.702 11.636,63.601 12.077,64.041 12.077,64.164 12.222,64.164 12.517,64.46 25.577,64.46 27.3,66.183 27.3,66.879 28.371,67.95 29.92,67.95 30.611,67.259 30.611,65.469 31.75,64.33 XP8.25@31.75,64.22
QSPI1_CS/PB0: R5.2 R53.2 XP10.1 | length 32.2
  Top Layer w0.2: v1@-19.67,54.277 -18.872,55.075 R53.2@-18.872,55.1 ; v1(-19.643,54.225) -19.643,54.117 -19.843,53.917 -19.843,45.015 -19.843,44.72 -18.518,43.395 -13.844,43.395 -13.533,43.705 R5.2@-12.323,43.705
  Bottom Layer w0.2: XP10.1@-29.21,56.6 -28.81,57 -27.273,57 -25.461,58.812 -22.647,58.812 -21.693,57.858 -21.693,56.276 v1(-19.643,54.225)
QSPI1_IO2/PB4: R3.2 R50.2 XP10.6 | length 43.9
  Top Layer w0.2: v1(-21.636,61.215) -22.232,60.619 -22.818,60.033 -22.818,59.205 -22.243,58.63 -22.243,43.706 -18.457,39.921 -13.584,39.921 -13.465,40.039 R3.2@-12.323,40.039 ; v1@-21.601,61.25 -20.551,62.3 R50.2@-18.872,62.3
  Bottom Layer w0.2: XP10.6@-31.75,61.68 -30.482,60.412 -22.439,60.412 v1(-21.636,61.215)
QSPI1_IO3/PB5: R25.1 R51.2 XP10.8 | length 47.5
  Top Layer w0.2: R51.2@-18.872,56.9 -18.872,56.875 -19.222,56.525 -19.247,56.525 -19.699,56.073 v1(-19.722,56.073) -20.243,55.552 -20.243,44.849 -20.243,44.535 -18.213,42.505 R25.1@-16.885,42.505
  Bottom Layer w0.2: XP10.8@-31.75,64.22 -33.47,64.22 -33.939,63.751 -33.939,56.429 -32.31,54.8 -27.337,54.8 -25.969,56.168 -23.018,56.168 -19.994,53.144 -19.394,53.144 -18.729,53.808 -18.729,55.08 v1(-19.722,56.073)
QSPI1_MISO/PB3: R7.2 R49.2 XP10.19 | length 52.1
  Top Layer w0.2: R49.2@-18.872,58.7 v1(-19.722,58.7) -20.643,57.779 -20.643,44.683 -20.643,44.369 -17.916,41.642 -13.894,41.642 -13.681,41.855 R7.2@-12.323,41.855
  Bottom Layer w0.2: XP10.19@-29.21,79.46 -27.531,77.781 -27.531,75.731 ; -27.53,75.73 -27.53,66.266 -26.676,65.412 -22.808,65.412 -19.722,62.325 v1(-19.722,58.7)
QSPI1_MOSI/PB2: R27.1 R48.2 XP10.3 XS6.8 | length 38.3
  Top Layer w0.2: XP10.3@-29.21,59.14 -26.67,59.14 XS6.8@-24.13,61.68 -23.136,60.686 ; R48.2@-18.872,64.1 -19.722,64.1 -23.136,60.686 ; R27.1@-16.885,38.914 -18.016,38.914 -22.642,43.541 -22.642,56.698 -22.86,56.916 -22.86,58.682 -23.218,59.039 -23.218,60.199 -23.136,60.281 -23.136,60.686
QSPI1_SCK/PB1: R26.1 R47.2 XP10.2 | length 36
  Top Layer w0.2: v1(-21.818,59.619) -21.818,59.521 -21.443,59.146 -21.443,44.038 -18.126,40.721 R26.1@-16.935,40.721 ; v1@-21.736,59.663 -21.693,59.706 -21.693,59.744 -20.937,60.5 R47.2@-18.872,60.5
  Bottom Layer w0.2: XP10.2@-31.75,56.6 -30.55,57.8 -28.821,57.8 -27.009,59.612 -21.825,59.612 v1(-21.818,59.619)
RES_BUT: C60.1 DD10.1 R80.1 SB2.1 SB2.2 | length 14.6
  Top Layer w0.3: SB2.1@-22.764,7.607 -17.839,7.607 SB2.2@-17.546,7.607 ; C60.1@-21.251,12.147 -20.957,11.853 -19.647,11.853 ; DD10.1@-19.647,13.017 -19.647,11.853 ; R80.1@-19.451,10.347 -19.647,10.543 -19.647,11.853 ; R80.1@-19.451,10.372 -19.451,9.513 -18.175,8.236 -18.175,7.85 -17.932,7.607 SB2.2@-17.546,7.607 ; SB2.2@-17.014,7.5 -17.438,7.5 SB2.2@-17.546,7.607 ; SB2.2@-17.014,7.607 -17.438,7.607 SB2.2@-17.546,7.607
RX_3/PB7: DD5.4 XP10.17 XS6.1 | length 47.7
  Top Layer w0.2: XP10.17@-29.21,76.92 -28.41,77.72 -27.355,77.72 -25.615,79.46 XS6.1@-24.13,79.46 -23.021,79.46 -19.928,76.367 v1(-19.928,75.377) ; DD5.4@3,62.505 3,63.352 3.785,64.138 4.006,64.138 4.746,64.877 4.746,65.59 v1(4.753,65.598)
  Bottom Layer w0.2: v1(-19.928,75.377) -17.325,75.377 -14.449,72.5 1.978,72.5 3.638,70.84 3.638,69.859 4.238,69.259 4.238,66.829 4.715,66.352 4.715,65.637 v1(4.753,65.598)
SCK_1/PA9: DD5.50 XP9.11 XS5.6 | length 35.4
  Top Layer w0.2: XP9.11@-29.21,42.37 -27.73,42.37 -25.18,44.92 XS5.6@-24.13,44.92 ; v1(-2.564,50.795) -2.564,50.904 -2.2,51.267 DD5.50@-2.2,52.695
  Bottom Layer w0.2: XS5.6@-24.13,44.92 -21.75,47.3 -17.795,47.3 -17.052,48.043 -13.638,48.043 -12.077,49.604 -6.519,49.604 -5.415,48.5 -4.879,48.5 -4.079,47.7 -3.581,47.7 -2.081,49.201 -2.081,50.313 v1(-2.564,50.795)
SCL_0/PA4: DD5.57 R75.2 XP9.3 XS5.10 | length 53.2
  Top Layer w0.2: XP9.3@-29.21,32.2 -26.65,34.76 XS5.10@-24.13,34.76 -22.55,34.76 -19.315,31.525 -17.091,31.525 -16.107,30.54 -16.107,30.181 R75.2@-15.818,29.893 ; DD5.57@0.6,52.695 0.6,50.107 1.042,49.665 1.042,49.282 v1(1.075,49.25)
  Bottom Layer w0.2: XS5.10@-24.13,34.76 -20.615,38.275 -17.239,38.275 -15.989,39.525 -13.345,39.525 -8.78,44.09 -1.187,44.09 0.325,45.601 0.325,46.628 1.075,47.378 v1(1.075,49.25)
SDA_0/PA5: DD5.56 XP9.5 XS5.9 | length 41
  Top Layer w0.2: XP9.5@-29.21,34.75 -26.66,37.3 XS5.9@-24.13,37.3 ; DD5.56@0.2,52.695 0.2,52.335 0.2,49.942 0.25,49.892 0.25,49.609 v1(0.327,49.532)
  Bottom Layer w0.2: XS5.9@-24.13,37.3 -22.263,37.3 -20.88,38.683 -17.397,38.683 -16.155,39.925 -13.511,39.925 -8.946,44.49 -1.353,44.49 -0.075,45.767 -0.075,46.794 0.475,47.344 0.475,48.752 0.327,48.9 v1(0.327,49.532)
TCK/PA0: DD5.61 R76.2 XP9.1 | length 48.1
  Top Layer w0.2: v1(-17.121,36.475) -17.013,36.475 -16.492,36.996 -15.897,36.996 R76.2@-15.859,37.034 ; DD5.61@2.2,52.695 2.2,50.831 3.786,49.246 v1(3.786,48.483)
  Bottom Layer w0.2: XP9.1@-29.21,29.66 -28.176,30.694 -27.62,30.694 -26.114,32.2 -22.889,32.2 -18.614,36.475 v1(-17.121,36.475) ; v1@-17.121,36.473 -16.611,36.473 -15.158,37.925 -12.682,37.925 -8.118,42.49 -0.524,42.49 1.925,44.939 1.925,45.965 3.786,47.826 v1(3.786,48.483)
TCLK/CSN: R69.2 R76.1 XP6.4 | length 36.8
  Top Layer w0.2: R76.1@-14.218,37.034 -14.218,37.009 -13.868,36.659 -13.843,36.659 -13.216,36.032 -13.216,35.416 v1(-11.605,33.806) ; v1@-11.621,33.806 -11.288,33.473 R69.2@-10.164,33.473
  Bottom Layer w0.2: XP6.4@-31.769,20.158 -30.481,21.445 -25.33,21.445 -23.971,22.804 -19.384,22.804 -18.602,23.586 -15.119,23.586 -13.853,24.852 -13.853,26.661 -12.451,28.063 -12.451,29.121 -10.204,31.368 -10.204,32.404 v1(-11.605,33.806)
TDI/MOSI: R64.2 R72.1 XP6.8 | length 37.7
  Top Layer w0.2: R72.1@-14.218,35.271 -14.218,35.246 -13.868,34.896 -13.843,34.896 -13.075,34.128 v1(-13.075,33.459) -11.32,31.704 R64.2@-10.164,31.704
  Bottom Layer w0.2: XP6.8@-29.229,20.158 -28.341,21.045 -25.165,21.045 -23.805,22.404 -19.218,22.404 -18.437,23.186 -14.953,23.186 -13.453,24.687 -13.453,26.496 -12.051,27.897 -12.051,28.956 -9.804,31.202 -9.804,33.029 -11.181,34.406 -12.129,34.406 v1(-13.075,33.459)
TDI/PA3: DD5.58 R72.2 XP9.6 | length 53.5
  Top Layer w0.2: v1(-21.089,36.953) -19.408,35.271 R72.2@-15.818,35.271 ; DD5.58@1,52.695 1,50.273 1.717,49.556 v1(1.717,48.772)
  Bottom Layer w0.2: XP9.6@-31.75,34.74 -31.607,34.883 -30.767,34.883 -29.708,35.942 -28.57,35.942 -26.028,33.4 -23.669,33.4 -22.55,34.52 -22.55,35.492 v1(-21.089,36.953) ; v1@-21.089,36.966 -20.18,37.875 -17.074,37.875 -15.824,39.125 -13.179,39.125 -8.615,43.69 -1.021,43.69 0.725,45.436 0.725,46.462 1.717,47.454 v1(1.717,48.772)
TDO/MISO: R65.2 R73.1 XP6.6 | length 31.4
  Top Layer w0.2: XP6.6@-30.608,20.048 XP6.6@-30.499,20.158 -29.611,21.045 -27.142,21.045 -24.773,23.414 -24.773,23.72 v1(-24.263,24.23) ; v1(-15.059,34.315) -15.049,34.315 -14.218,33.484 R73.1@-14.218,33.459 -14.218,33.434 -13.868,33.084 -13.843,33.084 -10.801,30.042 -10.292,30.042 R65.2@-10.168,29.918
  Bottom Layer w0.2: v1(-24.263,24.23) -24.263,29.463 -22.726,31 -22.334,31 -19.019,34.315 v1(-15.059,34.315)
TDO/PA2: DD5.59 R73.2 XP9.4 | length 53.5
  Top Layer w0.2: v1(-21.243,35.731) -18.971,33.459 R73.2@-15.818,33.459 ; DD5.59@1.4,52.695 1.4,51.066 1.4,50.5 2.247,49.653 2.247,49.37 v1(2.324,49.294)
  Bottom Layer w0.2: XP9.4@-31.75,32.2 -31.705,32.245 -30.767,32.245 -29.712,33.3 -26.494,33.3 -26.194,33 -23.504,33 -22.038,34.465 -22.038,34.936 v1(-21.243,35.731) -21.243,35.783 -19.551,37.475 -16.908,37.475 -15.658,38.725 -13.014,38.725 -8.449,43.29 -0.856,43.29 1.125,45.27 1.125,46.297 2.317,47.489 2.317,49.287 v1(2.324,49.294)
TIM0_PWM0/PA12: DD5.43 VT2.3 XP9.18 XS5.2 | length 41.1
  Top Layer w0.2: XP9.18@-31.75,49.99 -30.54,51.2 -28.857,51.2 -25.1,54.957 -24.253,54.957 XS5.2@-24.13,55.08 ; VT2.3@-6.698,46.043 -6.823,46.043 -7.023,46.243 -7.023,48.99 -6.457,49.556 -6.457,51.03 -5.995,51.492 -5.995,51.964 -5.669,52.29 v1(-5.669,52.897) -5.715,52.942 -5.715,53.683 -5.598,53.8 DD5.43@-4.905,53.8
  Bottom Layer w0.2: XS5.2@-24.13,55.08 -23.021,55.08 -20.659,52.718 -16,52.718 -15.415,52.134 -14.918,52.134 -13.057,53.995 -11.096,53.995 -10.245,54.845 -8.024,54.845 -7.838,55.031 -7.324,55.031 -7.035,54.742 -6.887,54.742 -5.669,53.525 v1(-5.669,52.897)
TIM1_PWM0/PB12: DD5.86 XP10.5 XS6.7 | length 65.6
  Top Layer w0.2: XP10.5@-29.21,61.68 -29.027,61.863 -28.237,61.863 -25.88,64.22 XS6.7@-24.13,64.22 ; DD5.86@4.905,61 6.607,61 7.429,61.821 9.341,61.821 v1(10.286,62.766)
  Bottom Layer w0.2: XS6.7@-24.13,64.22 -22.22,64.22 -20.322,62.322 -20.322,58.451 -17.579,55.709 -17.579,54.424 -16.889,53.734 -14.45,53.734 -13.389,54.795 -11.427,54.795 -9.022,57.2 -8.281,57.2 -8.081,57.4 -6.794,57.4 -5.739,56.346 -5.739,55.362 -2.572,52.195 3.254,52.195 5.955,54.896 5.955,59.897 8.824,62.766 v1(10.286,62.766)
TIM1_PWM1/PB13: DD5.85 XP10.7 XS6.6 | length 80.6
  Top Layer w0.2: XP10.7@-29.21,64.22 -29.057,64.373 -28.227,64.373 -25.84,66.76 XS6.6@-24.13,66.76 ; DD5.85@4.905,60.6 5.925,60.6 6.773,60.6 7.594,61.421 9.79,61.421 11,62.632 11,69.4 10.61,69.79 8.873,69.79 8.556,70.108 v1(8.512,70.108)
  Bottom Layer w0.2: XS6.6@-24.13,66.76 -24.317,66.947 -24.317,67.729 -26.03,69.443 -26.03,80.127 -25.197,80.96 -23.063,80.96 -20.673,78.57 -9.991,78.57 -9.951,78.53 4.436,78.53 4.768,78.53 6.623,76.675 6.623,76.343 6.623,70.074 7.186,69.512 8.006,69.512 8.512,70.019 v1(8.512,70.108)
TIM1_PWM3/PB15: DD5.83 XP10.11 XS6.4 | length 73.8
  Top Layer w0.2: XP10.11@-29.21,69.3 -28.977,69.533 -28.287,69.533 -25.98,71.84 XS6.4@-24.13,71.84 ; DD5.83@4.905,59.8 7.247,59.8 7.647,60.2 8.718,60.2 8.939,60.421 v1(9.035,60.421) ; v1(11.6,69) 11.6,63.916 12.4,63.116 12.425,63.116 12.583,62.958 v1(12.691,62.958)
  Bottom Layer w0.2: XS6.4@-24.13,71.84 -25.23,72.94 -25.23,76.464 -25.23,77.617 -24.647,78.2 -21.435,78.2 -21.005,77.77 -10.322,77.77 -10.282,77.73 4.437,77.73 5.823,76.343 5.823,69.743 6.854,68.712 8.531,68.712 9.515,69.696 10.904,69.696 v1(11.6,69) ; v1(9.035,60.421) 9.439,60.825 10.891,60.825 12.436,62.371 12.436,62.595 12.691,62.85 v1(12.691,62.958)
TMS/PA1: DD5.60 R74.2 XP9.2 | length 55.4
  Top Layer w0.2: v1(-21.438,34.5) -20.716,33.777 -18.864,31.925 -16.084,31.925 R74.2@-15.723,31.565 ; DD5.60@1.8,52.695 1.8,50.666 3.104,49.361 3.104,48.942 v1(3.119,48.927)
  Bottom Layer w0.2: XP9.2@-31.75,29.66 -31.482,29.928 -30.943,29.928 -29.777,31.094 -27.786,31.094 -26.28,32.6 -23.338,32.6 -21.362,34.576 -18.863,37.075 -16.742,37.075 -15.492,38.325 -12.848,38.325 -8.283,42.89 -0.69,42.89 1.525,45.104 1.525,46.131 3.119,47.725 v1(3.119,48.927)
TMS/SCK: R66.2 R74.1 XP6.2 | length 31.1
  Top Layer w0.2: R74.1@-14.218,31.659 -14.218,31.634 -13.868,31.284 -13.843,31.284 -13.132,30.573 -13.132,28.29 -10.575,28.29 R66.2@-10.411,28.126
  Bottom Layer w0.2: XP6.2@-33.039,20.158 -31.351,21.845 -25.496,21.845 -24.137,23.204 -19.55,23.204 -18.768,23.986 -15.285,23.986 -14.253,25.018 -14.253,27.11 v1(-13.102,28.26)
TRST: R67.2 R75.1 R117.2 | length 7.8
  Top Layer w0.2: R75.1@-14.218,29.893 R117.2@-14.218,28.099 -14.218,26.898 -11.87,24.55 R67.2@-10.411,24.55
